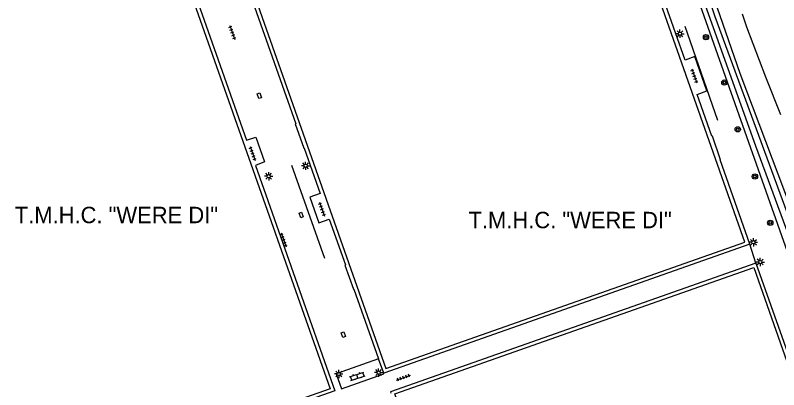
# Model space of a CAD drawing. Extents: x 135990 to 139000, y 393500 to 396000.
# Drawn here: x 135990.3 to 136106.6, y 395847.7 to 395904.7 of the extents above; entities that cross this region are included whole.
import ezdxf

# ---------------------------------------------------------------- set-up
doc = ezdxf.new("R2010")
doc.units = 0
for name, color, linetype in [('gg-afsc-hekwerk', 7, 'Continuous'), ('gg-knt-BGT kruinlijn', 7, 'Continuous'), ('gg-knt-verharding', 7, 'Continuous'), ('gg-kntw-bovenkant insteek waterloop', 7, 'Continuous'), ('gg-kntw-waterlijn', 7, 'Continuous'), ('gt-anno-naam bijzondere bebouwing', 7, 'Continuous'), ('gt-anno-overige text', 7, 'Continuous'), ('gt-symb-boom', 7, 'Continuous'), ('gt-symb-klinker verharding', 7, 'Continuous'), ('gt-symb-kolk center center', 7, 'Continuous'), ('gt-symb-lichtmast', 7, 'Continuous'), ('gt-symb-tegel verharding', 7, 'Continuous')]:
    doc.layers.add(name, color=color, linetype=linetype)

# ---------------------------------------------------------------- blocks, each defined once
blk = doc.blocks.new('gt0-LMAST')
at = {"layer": 'gt-symb-lichtmast'}
for p, q in [((-0.18, 0.17), (-0.45, 0.44)), ((-0.01, 0.25), (-0.01, 0.62)), ((0.17, 0.17), (0.44, 0.44)), ((-0.26, 0), (-0.63, 0)), ((-0.18, -0.18), (-0.45, -0.45)), ((-0.01, -0.25), (-0.01, -0.63)), ((0.44, -0.45), (0.17, -0.18)), ((0.24, 0), (0.62, 0))]:
    blk.add_line(p, q, dxfattribs=at)
blk.add_circle((-0.01, 0), 0.25, dxfattribs=at)
blk = doc.blocks.new('gt0-BOOM')
at = {"layer": 'gt-symb-boom'}
for radius in [0.4, 0.2]:
    blk.add_circle((0, 0), radius, dxfattribs=at)
blk = doc.blocks.new('gt0-TEG1')
at = {"layer": 'gt-symb-tegel verharding'}
for p, q in [((-1.12, 0), (1.12, 0)), ((-0.9, -0.25), (-0.9, 0.25)), ((-0.45, -0.25), (-0.45, 0.25)), ((0, -0.25), (0, 0.25)), ((0.45, -0.25), (0.45, 0.25)), ((0.9, -0.25), (0.9, 0.25))]:
    blk.add_line(p, q, dxfattribs=at)
blk = doc.blocks.new('gt0-KL1')
at = {"layer": 'gt-symb-klinker verharding'}
for p, q in [((-1.15, 0.3), (1.15, 0.3)), ((-1, -0.3), (-1, 0.3)), ((-0.5, 0.3), (-0.5, 0.45)), ((0, -0.3), (0, 0.3)), ((0.5, 0.3), (0.5, 0.45)), ((1, -0.3), (1, 0.3)), ((-1.15, -0.3), (1.15, -0.3)), ((-0.5, -0.45), (-0.5, -0.3)), ((0.5, -0.45), (0.5, -0.3))]:
    blk.add_line(p, q, dxfattribs=at)
blk = doc.blocks.new('gt0-KOLKCC')
at = {"layer": 'gt-symb-kolk center center'}
blk.add_lwpolyline([(-0.38, 0.2), (0.38, 0.2), (0.38, -0.2), (-0.38, -0.2)], close=True, dxfattribs=at)

msp = doc.modelspace()

# ---------------------------------------------------------------- linework, layer by layer
at = {"layer": 'gg-afsc-hekwerk'}
for p, q in [((136097.312, 395888.691), (136092.341, 395903.002)), ((136037.438, 395867.676), (136032.448, 395881.827)), ((136102.191, 395869.835), (136046.437, 395850.196)), ((136103.149, 395866.98), (136111.254, 395843.918)), ((136046.437, 395850.196), (136045.653, 395852.41))]:
    msp.add_line(p, q, dxfattribs=at)
for points in [[(136076.591, 395957.119), (136076.633, 395957.112), (136095.22, 395904.613), (136111.438, 395858.672)], [(136076.591, 395957.119), (136076.633, 395957.112), (136095.22, 395904.613), (136111.438, 395858.672)], [(136005.834, 395941.555), (136025.534, 395885.678), (136026.927, 395886.17), (136028.274, 395882.376), (136026.903, 395881.831), (136038.97, 395847.543), (136000, 395833.796)], [(136026.769, 395905.995), (136033.025, 395888.2), (136032.944, 395888.172), (136034.249, 395884.466), (136034.318, 395884.49), (136036.762, 395877.56), (136035.173, 395876.991), (136036.555, 395873.118), (136038.124, 395873.669), (136040.592, 395866.7), (136040.527, 395866.677), (136041.822, 395862.992), (136041.896, 395863.018), (136045.653, 395852.41)], [(136102.191, 395869.835), (136097.67, 395882.689), (136097.751, 395882.718), (136096.501, 395886.306), (136096.409, 395886.274), (136094.164, 395892.656), (136095.664, 395893.183), (136093.819, 395898.438), (136092.335, 395897.857), (136089.429, 395906.172)], [(136103.149, 395866.98), (136047.444, 395847.368), (136047.508, 395847.185)]]:
    msp.add_lwpolyline(points, dxfattribs=at)
at = {"layer": 'gg-knt-BGT kruinlijn'}
msp.add_lwpolyline([(136101.02, 395904.901), (136101.725, 395902.928), (136104.62, 395895.348), (136106.892, 395889.582)], dxfattribs=at)
at = {"layer": 'gg-knt-verharding'}
msp.add_line((136103.149, 395866.98), (136102.191, 395869.835), dxfattribs=at)
for points in [[(136046.773, 395850.912), (136101.471, 395870.164), (136068.815, 395962.949), (136014.049, 395943.734), (136046.773, 395850.912)], [(136000, 395938.921), (136005.487, 395940.859), (136038.267, 395847.842), (136000, 395834.364)], [(136048.132, 395847.054), (136102.827, 395866.304), (136135.438, 395773.474), (136080.76, 395754.222), (136048.132, 395847.054)], [(136045.653, 395852.41), (136039.187, 395850.113), (136039.992, 395847.842), (136046.469, 395850.104), (136046.437, 395850.196)]]:
    msp.add_lwpolyline(points, dxfattribs=at)
at = {"layer": 'gg-kntw-bovenkant insteek waterloop'}
msp.add_lwpolyline([(136114.344, 395859.824), (136100.745, 395895.836), (136087.665, 395933.499), (136076.623, 395963.97), (136074.337, 395963.35)], dxfattribs=at)
at = {"layer": 'gg-kntw-waterlijn'}
msp.add_lwpolyline([(136113.492, 395859.486), (136096.948, 395904.455), (136087.39, 395933.074), (136076.227, 395962.85), (136075.297, 395962.501), (136103.1, 395884.834), (136112.551, 395859.113)], dxfattribs=at)

# ---------------------------------------------------------------- block references
at = {"layer": 'gt-symb-boom'}
for p in [(136095.532, 395901.373), (136098.326, 395894.461), (136100.368, 395887.336), (136102.991, 395880.154), (136105.324, 395873.1)]:
    msp.add_blockref('gt0-BOOM', p, dxfattribs=at)
at = {"layer": 'gt-symb-klinker verharding', "rotation": 18.906060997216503}
msp.add_blockref('gt0-KL1', (136042.415, 395849.728), dxfattribs=at)
at = {"layer": 'gt-symb-kolk center center'}
for p, rotation in [((136027.491, 395892.448), -70.57742275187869), ((136033.851, 395874.302), -70.75603718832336), ((136040.283, 395856.066), -69.85763553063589)]:
    msp.add_blockref('gt0-KOLKCC', p, dxfattribs=dict(at, rotation=rotation))
at = {"layer": 'gt-symb-lichtmast'}
for p in [(136091.577, 395901.895), (136034.547, 395881.786), (136028.919, 395880.201), (136102.767, 395870.142), (136103.804, 395867.134), (136039.59, 395850.086), (136045.66, 395850.304)]:
    msp.add_blockref('gt0-LMAST', p, dxfattribs=at)
at = {"layer": 'gt-symb-tegel verharding'}
for p, rotation in [((136023.372, 395902.096), -70.49642676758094), ((136093.747, 395895.472), -70.49642676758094), ((136026.477, 395883.674), -70.49642676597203), ((136037.033, 395875.188), -70.49642676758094), ((136031.198, 395870.518), -70.60447167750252), ((136049.453, 395849.521), 19.214311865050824)]:
    msp.add_blockref('gt0-TEG1', p, dxfattribs=dict(at, rotation=rotation))

# ---------------------------------------------------------------- texts
at = {"layer": 'gt-anno-naam bijzondere bebouwing'}
msp.add_text('T.M.H.C. "WERE DI"', height=2.5, dxfattribs=at).set_placement((136059.351, 395872.28))
at = {"layer": 'gt-anno-overige text'}
msp.add_text('T.M.H.C. "WERE DI"', height=2.5, dxfattribs=at).set_placement((135990.225, 395873.047))

doc.saveas('drawing.dxf')
